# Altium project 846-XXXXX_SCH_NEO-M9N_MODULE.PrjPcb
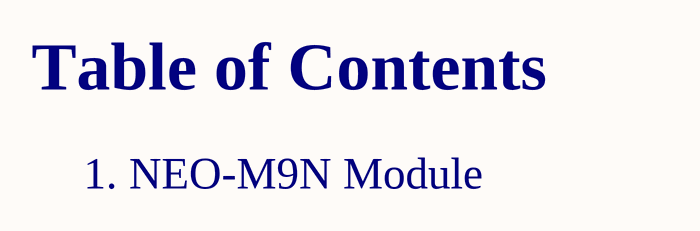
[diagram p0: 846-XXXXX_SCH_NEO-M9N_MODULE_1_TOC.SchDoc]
prjCompanyName: Meta Platforms Technologies, LLC.; prjContactAddress1: 9845 Willows Road NE; prjContactAddress2: Redmond, WA 98052; prjContactEmail: Contact Email; prjContactPhone: (...)-...-....; prjElectricalEngineer: Electical Engineer; prjElectricalEngineerEmail: Electical Engineer Email; prjLayoutEngineer: Layout Engineer; prjLayoutEngineerEmail: Layout Engineer Email; prjMechanicalEngineer: Mechanical Engineer; prjMechanicalEngineerEmail: Mechanical Engineer Email; prjPCB_IPN: 844-XXXXX-XX; prjPCB_Name: PCB Name; prjPCB_Revision: X1; prjProjectName: Project Name; prjSchematic_IPN: 846-XXXXX-XX; prjSchematic_Revision: X1; XprjPCBA_IPN: Set v_prjPCBA_IPN in variant parameters; XprjPCBA_Revision: Set v_prjPCBA_Revision in variant parameters
2 sheets, 33 parts. Net scope: global (net labels, ports and power ports of the same name join across sheets).
Board file: 844-XXXXX_FAB_NEO-M9N_MODULE.PcbDoc
Sheets:
  846-XXXXX_SCH_NEO-M9N_MODULE_1_TOC.SchDoc
  846-XXXXX_SCH_NEO-M9N_MODULE_2_RECEIVER.SchDoc

## Sheet 846-XXXXX_SCH_NEO-M9N_MODULE_1_TOC.SchDoc: NOT USED
size A; Date: NOT USED; ApprovedBy: NOT USED; CheckedBy: NOT USED; Author: NOT USED; CompanyName: NOT USED; DrawnBy: NOT USED; Engineer: NOT USED; Organization: NOT USED; Address1: NOT USED; Address2: NOT USED; Address3: NOT USED; Address4: NOT USED; DocumentNumber: Use Project Parameter prjSchematic_IPN; Revision: NOT USED; SheetNumber: 1; SheetTotal: 2; sch_PageDescription: Page Description; sch_PageTitle: Page Title; PageDate: NOT USED

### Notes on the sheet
- Table of Contents
- 1. NEO-M9N Module

## Sheet 846-XXXXX_SCH_NEO-M9N_MODULE_2_RECEIVER.SchDoc: NOT USED
size A; ApprovedBy: NOT USED; CheckedBy: NOT USED; Author: NOT USED; CompanyName: NOT USED; DrawnBy: NOT USED; Engineer: NOT USED; Organization: NOT USED; Address1: NOT USED; Address2: NOT USED; Address3: NOT USED; Address4: NOT USED; Revision: NOT USED; SheetNumber: 2; SheetTotal: 2; sch_PageDescription: sch_PageDescription; sch_PageTitle: sch_PageTitle
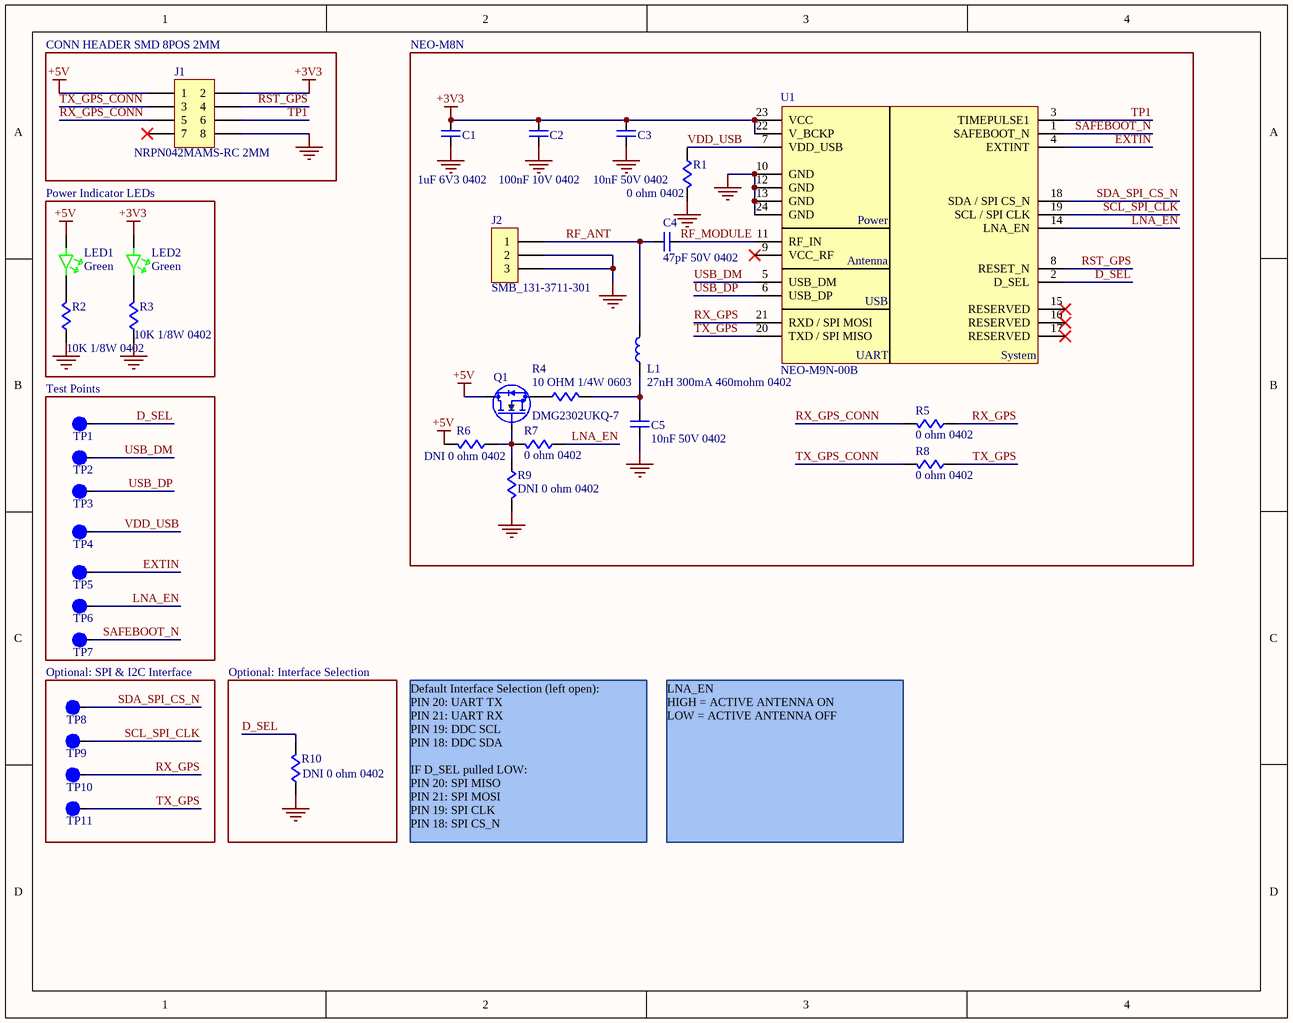
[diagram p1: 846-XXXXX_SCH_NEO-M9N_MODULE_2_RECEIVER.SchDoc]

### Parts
C1  1uF 6V3 0402  [c0402]
C2  100nF 10V 0402  [c0402]
C3  10nF 50V 0402  [c0402]
C4  47pF 50V 0402  [c0402]
C5  10nF 50V 0402  [c0402]
J1  NRPN042MAMS-RC 2MM  [CONN_NRPN042MAMS-RC]
J2  SMB_131-3711-301  [CONN_131-3711-301]
L1  27nH 300mA 460mohm 0402  [L0402]
LED1  Green  [led0603]
LED2  Green  [led0603]
Q1  DMG2302UKQ-7  [SOT23]
R1  0 ohm 0402  [r0402]
R2  10K 1/8W 0402  [r0402]
R3  10K 1/8W 0402  [r0402]
R4  10 OHM 1/4W 0603  [r0603]
R5  0 ohm 0402  [r0402]
R6  DNI 0 ohm 0402  [r0402]
R7  0 ohm 0402  [r0402]
R8  0 ohm 0402  [r0402]
R9  DNI 0 ohm 0402  [r0402]
R10  DNI 0 ohm 0402  [r0402]
TP1  1MM  [TP1MM]  (value not drawn)  (no BOM)
TP2  1MM  [TP1MM]  (value not drawn)  (no BOM)
TP3  1MM  [TP1MM]  (value not drawn)  (no BOM)
TP4  1MM  [TP1MM]  (value not drawn)  (no BOM)
TP5  1MM  [TP1MM]  (value not drawn)  (no BOM)
TP6  1MM  [TP1MM]  (value not drawn)  (no BOM)
TP7  1MM  [TP1MM]  (value not drawn)  (no BOM)
TP8  1MM  [TP1MM]  (value not drawn)  (no BOM)
TP9  1MM  [TP1MM]  (value not drawn)  (no BOM)
TP10  1MM  [TP1MM]  (value not drawn)  (no BOM)
TP11  1MM  [TP1MM]  (value not drawn)  (no BOM)
U1  NEO-M9N-00B  [IC_NEO-M9N]

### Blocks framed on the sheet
CONN HEADER SMD 8POS 2MM: J1
NEO-M8N: C1-C5 J2 L1 Q1 R1 R4-R9 U1
Power Indicator LEDs: LED1 LED2 R2 R3
Test Points: TP1-TP7
Optional: SPI & I2C Interface: TP8-TP11
Optional: Interface Selection: R10

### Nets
+3V3: C1.2 C2.2 C3.2 J1.2 LED2.1 U1.22(V_BCKP) U1.23(VCC)
+5V: J1.1 LED1.1 Q1.2(D) R6.2
GND: C1.1 C2.1 C3.1 C5.1 J1.8 J2.2 J2.3 R1.2 R2.1 R3.1 R9.2 R10.1 U1.10(GND) U1.12(GND) U1.13(GND) U1.24(GND)
D_SEL: R10.2 TP1.1 U1.2(D_SEL)
EXTIN: TP5.1 U1.4(EXTINT)
LNA_EN: R7.1 TP6.1 U1.14(LNA_EN)
RF_ANT: C4.1 J2.1 L1.2
RF_MODULE: C4.2 U1.11(RF_IN)
RST_GPS: J1.4 U1.8(RESET_N)
RX_GPS: R5.1 TP10.1 U1.21(RXD_/_SPI_MOSI)
RX_GPS_CONN: J1.5 R5.2
SAFEBOOT_N: TP7.1 U1.1(SAFEBOOT_N)
SCL_SPI_CLK: TP9.1 U1.19(SCL_/_SPI_CLK)
SDA_SPI_CS_N: TP8.1 U1.18(SDA_/_SPI_CS_N)
TP1: J1.6 U1.3(TIMEPULSE1)
TX_GPS: R8.1 TP11.1 U1.20(TXD_/_SPI_MISO)
TX_GPS_CONN: J1.3 R8.2
USB_DM: TP2.1 U1.5(USB_DM)
USB_DP: TP3.1 U1.6(USB_DP)
VDD_USB: R1.1 TP4.1 U1.7(VDD_USB)
NetC5_2: C5.2 L1.1 R4.2
NetLED1_2: LED1.2 R2.2
NetLED2_2: LED2.2 R3.2
NetQ1_1: Q1.1(G) R6.1 R7.2 R9.1
NetQ1_3: Q1.3(S) R4.1

Not connected (* = marked no-connect by the designer): J1 7*; U1 9(VCC_RF)* 15(RESERVED)* 16(RESERVED)* 17(RESERVED)*

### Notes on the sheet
- Default Interface Selection (left open):
  PIN 20: UART TX
  PIN 21: UART RX
  PIN 19: DDC SCL
  PIN 18: DDC SDA
  IF D_SEL pulled LOW:
  PIN 20: SPI MISO
  PIN 21: SPI MOSI
  PIN 19: SPI CLK
  PIN 18: SPI CS_N
- LNA_EN
  HIGH = ACTIVE ANTENNA ON
  LOW = ACTIVE ANTENNA OFF

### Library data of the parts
C1 = CAP CER 1UF 6.3V X7R 0402: 0402 1 uF 6.3 V ±10% Tolerance X7R Multilayer Ceramic Capacitor; Manufacturer: Murata; Manufacturer Part Number: GRM155R70J105KA12J; Voltage Rating: 6.3V
C2 = CAP CER 0.1UF 10V X7R 0402: CL05 Series 0.1 uF 10 V ±10 % Tolerance X7R SMT Multilayer Ceramic Capacitor; Manufacturer: Samsung; Manufacturer Part Number: CL05B104KP5NNNC; Tolerance: 10%
C3 C5 = CAP CER 10000PF 50V X7R 0402: Manufacturer: Murata; Manufacturer Part Number: GCM155R71H103KA55D; Tolerance: 10%
C4 = CAP CER 47PF 50V C0G/NPO 0402: 0402 47 pF 50 V ±5 % Tolerance NP0 SMT Multilayer Ceramic Capacitor; Manufacturer: Yageo; Manufacturer Part Number: CC0402JRNPO9BN470; Tolerance: 5%; Dielectric: C0G; Insulation Resistance: 100GR
J1 = CONN_NRPN042MAMS-RC: Dual Row 8 Position 2 mm Pitch Surface Mount Header; Manufacturer: Sullins; Number of Positions: 8; Connector Type: Male Pin; Pitch: 0.079inch
J2 = CONN_131-3711-301: Rf Coaxial Board Mount Connector; Manufacturer: Bel Cinch; Body Material: Brass; Plating: Nickel; Body Plating: Gold; Dielectric Material: PTFE; Impedance: 50R; Voltage Rating: 335V; Gender: Female; Frequency: 4Hz; Connector Type: SMB,Male Pin; Max Frequency: 4GHz; Polarity: Reverse; Operating Frequency: 0 to 4 Hz to GHz
L1 = FIXED IND 27NH 350MA 460MOHM SMD: Inductor RF Chip Multi-Layer 27nH 5% 100MHz 8Q-Factor Air 300mA 460mOhm DCR 0402 Paper T/R; Manufacturer: Murata; Manufacturer Part Number: LQG15HS27NJ02D; Shielding: Unshielded; Self Resonant Frequency: 1.7GHz; Q Factor: 8; DC Resistance (DCR): 460mR
LED1 LED2 = LED GREEN CLEAR CHIP SMD: LED High-Power Uni-Color Green 574nm 2-Pin Chip LED T/R; Manufacturer: Vishay Lite-On; Manufacturer Part Number: LTST-C190KGKT; Lens Color: Colorless; Lens Style: Diffused,Colorless,Rectangular,Clear; Forward Voltage: 2V; Forward Current: 30mA; Luminous Intensity: 35mcd; Viewing Angle: 130°; Power Rating: 75mW; Dominant Wavelength: 571nm; Test Current: 20mA; Lens Transparency: Clear; Number of Elements: 1; Reverse Voltage: 5V
Q1 = DMG2302UKQ-7: N-Channel 20 V 2.8A (Ta) 660mW (Ta) Surface Mount SOT-23-3; Mfr_Name: Diodes Inc; Manufacturer: Diodes; Type: DEV; Drain to Source Voltage (Vdss): 20V; Rds On Max: 90mR; Input Capacitance: 130pF
R1 R5-R10 = RES 0 OHM JUMPER 1/16W 0402: RES SMD 0 OHM JUMPER 1/16W 0402; Manufacturer: Yageo; Manufacturer Part Number: RC0402JR-070RL; Resistance: 0mR; Power Rating: 62.5mW; Tolerance: 5%; Voltage Rating: 50V; Max Power Dissipation: 63mW; Temperature Coefficient: 200ppm/°C
R2 R3 = RES 10K OHM 1% 1/8W 0402: Res Thick Film 0402 10K Ohm 1% 0.125W(1/8W) ±100ppm/°C Pad SMD T/R; Manufacturer: TE Connectivity; Manufacturer Part Number: CRGP0402F10K; Resistance: 10kR; Max Power Dissipation: 125mW
R4 = RES SMD 10 OHM 1% 1/4W 0603: Res Surge Chip Thick Film 0603 10 Ohm 1% 1/4W ±200ppm/°C Molded Paper T/R; Manufacturer: Yageo; Manufacturer Part Number: SR0603FR-7T10RL
TP1-TP11 = TP_1MM: Test Point 1MM diameter
U1 = IC NEO-M9N-00B: GNSS module, Flash, TCXO, SAW, LNA, LCC, 12x16 mm Professional Grade; Manufacturer: u-blox

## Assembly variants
845-XXXXX_PCBA_projectname: not fitted R6 R9 R10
